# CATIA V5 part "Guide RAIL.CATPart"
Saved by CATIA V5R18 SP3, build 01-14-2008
Part number: Moving Guide Rail
Bounding box of the stored display mesh (mm): x 0 to 20, y -170 to 170, z -7.5 to 7.5
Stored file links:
  E:\#00 CATIA V5 Movie\#03 CATIA V5 Data\#07 KIN\Balance Unit (1)\Guide RAIL.CATPart
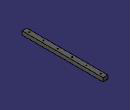
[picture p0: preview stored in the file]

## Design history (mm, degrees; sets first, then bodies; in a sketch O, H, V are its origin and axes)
Body1 (main body)
  Sketch1 on yz-plane, origin (0, 0, 0), H (0, 1, 0), V (0, 0, 1)
    line L1 (170, 7.5) -> (170, -7.5)
    line L2 (170, -7.5) -> (-170, -7.5)
    line L3 (-170, -7.5) -> (-170, 7.5)
    line L4 (-170, 7.5) -> (170, 7.5)
    distance L2 L4 = 15
    distance L1 L3 = 340
    vertical: L1 V, L3 V
    horizontal: L2 H, L4 H
    equidistance: L1 L3 O, L2 L4 O
  Pad1: profile Sketch1, direction (1, 0, 0), length 20
  Sketch2 on face of Pad1 from Sketch1.L4, origin (10, 150, 7.5), H (1, 0, 0), V (0, 1, 0)
    point P1 (0, 0)
    reference projected point E1 (0, 0) from Sketch3.P1
    coincidence: E1 P1
  Hole1: placed by Sketch2, at (10, 150, 7.5) direction (0, 0, -1), diameter 4.134, through (limit type 6), threaded "M5", thread diameter 5, thread depth 10, pitch 0.8
  Sketch3 on face of Pad1 from Sketch1.L4, origin (0, 0, 7.5), H (1, 0, 0), V (0, 1, 0)
    point P1 (10, 150)
    reference projected line E1 (0, 170) -> (20, 170) from edge [face of Pad1 from Sketch1.L4 | face of Pad1 from Sketch1.L1]
    point P2 (10, 90)
    point P3 (10, 30)
    point P4 (10, -30)
    point P5 (10, -90)
    point P6 (10, -150)
    distance P1 E1 = 20
    distance P1 V = 10
  UserPattern1: of Hole1, copies 6, at the points of Sketch3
